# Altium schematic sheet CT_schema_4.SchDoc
size 289 x 159 mm
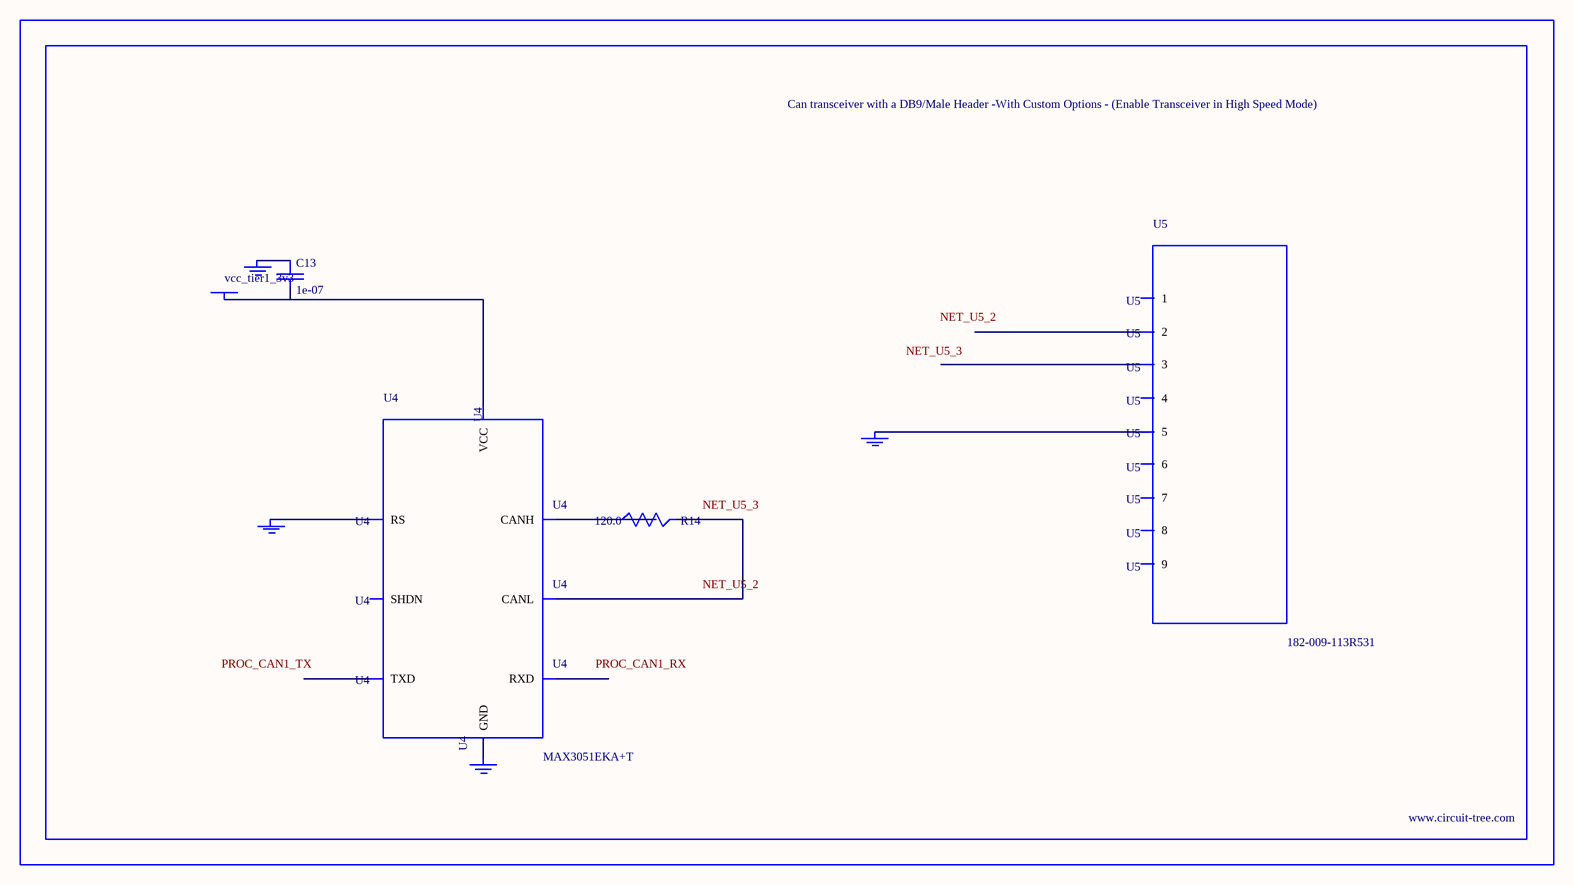
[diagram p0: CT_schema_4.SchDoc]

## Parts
BORDER3  (no value)
C13  1e-07  [C0402]
GND_INSTANCE_3_0  (no value)
GND_INSTANCE_3_1  (no value)
GND_INSTANCE_3_2  (no value)
GND_INSTANCE_3_3  (no value)
POWER_INSTANCE_3_0  vcc_tier1_3v3
R14  120.0  [R0603]
U4  MAX3051EKA+T  [SOT-23-8]
U5  182-009-113R531  [182-009-MALE]

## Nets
NetC13_1: C13.1 GND_INSTANCE_3_0.0(GND)
NetC13_2: C13.2 POWER_INSTANCE_3_0.0(PWR) U4.3(VCC)
NetGND_INSTANCE_3_1_0: GND_INSTANCE_3_1.0(GND) U4.8(RS)
NetGND_INSTANCE_3_2_0: GND_INSTANCE_3_2.0(GND) U4.2(GND)
NetGND_INSTANCE_3_3_0: GND_INSTANCE_3_3.0(GND) U5.5
NetR14_1: R14.1 U4.7(CANH)
NetR14_2: R14.2 U4.6(CANL)

Not connected (* = marked no-connect by the designer): U4 1(TXD) 4(RXD) 5(SHDN); U5 1 2 3 4 6 7 8 9

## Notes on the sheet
- Labels drawn without touching a wire or pin: NET_U5_2, NET_U5_3, PROC_CAN1_RX, PROC_CAN1_TX

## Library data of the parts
BORDER3 = BORDER_PAGE3
C13 = C0402C104K3RACTU
GND_INSTANCE_3_0-GND_INSTANCE_3_3 = GND
POWER_INSTANCE_3_0 = PWR
R14 = RC0603JR-07120RL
